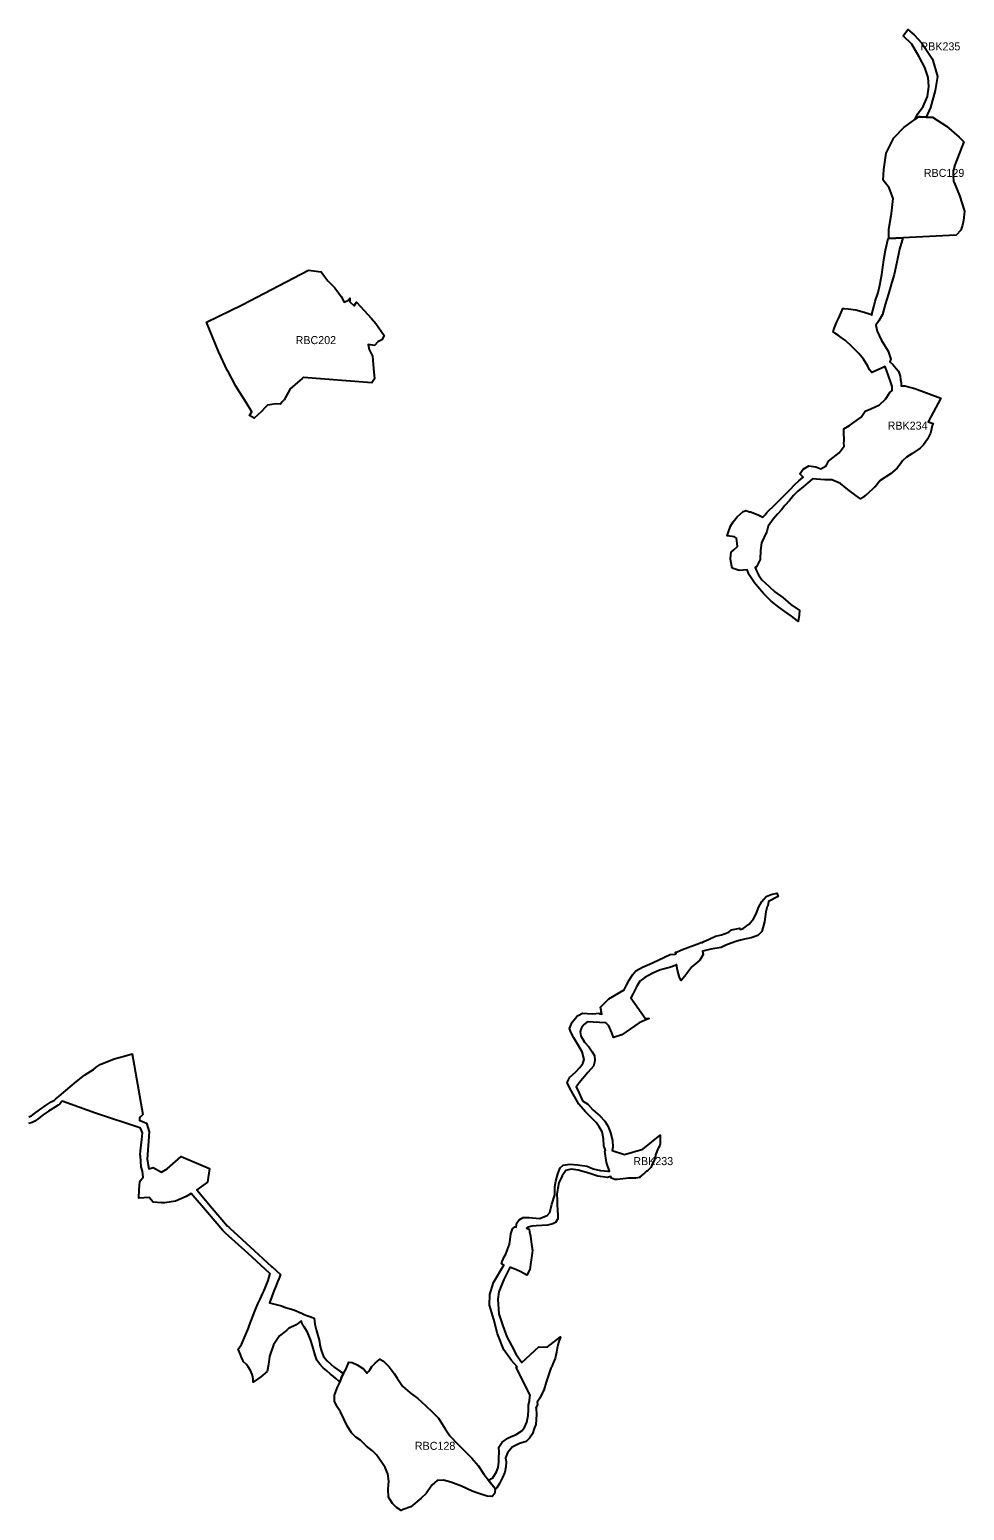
# Model space of a CAD drawing. Extents: x -559776 to -467147, y -1204122 to -1132159.
# Drawn here: x -511258 to -505422, y -1199487 to -1190238 of the extents above; entities that cross this region are included whole.
import ezdxf

# ---------------------------------------------------------------- set-up
doc = ezdxf.new("R2010")
doc.units = 0
doc.layers.add('regionalni_biocentrum_biokoridor', color=7, linetype='Continuous')

msp = doc.modelspace()

# ---------------------------------------------------------------- linework, layer by layer
at = {"layer": 'regionalni_biocentrum_biokoridor'}
for points in [[(-505660.89, -1190784.55), (-505698.22, -1190783.5), (-505708, -1190783.25), (-505730.03, -1190799.2), (-505714.05, -1190765.9), (-505678.12, -1190719.04), (-505651.57, -1190656.56), (-505643.76, -1190594.08), (-505646.88, -1190536.28), (-505668.75, -1190473.8), (-505703.11, -1190408.2), (-505749.97, -1190328.53), (-505802.69, -1190275.82), (-505773.92, -1190238.01), (-505735.92, -1190270.74), (-505687.49, -1190322.28), (-505620.33, -1190422.25), (-505589.09, -1190530.03), (-505603.15, -1190619.07), (-505632.82, -1190725.29)], [(-505660.89, -1190784.55), (-505626.97, -1190785.5), (-505620.62, -1190785.62), (-505532.84, -1190840.37), (-505455.06, -1190909.37), (-505424.16, -1190939.5), (-505482.41, -1191088.37), (-505482.55, -1191092.29), (-505491.41, -1191120.17), (-505491.14, -1191150.61), (-505488.41, -1191185.08), (-505486.11, -1191190.03), (-505486.19, -1191192.25), (-505451, -1191273.62), (-505421.55, -1191372.82), (-505426, -1191429.36), (-505432.27, -1191460.42), (-505444.45, -1191491.07), (-505473.22, -1191522.62), (-505806.41, -1191538.25), (-505893.34, -1191542.25), (-505892.47, -1191483.87), (-505876.34, -1191387.12), (-505866.53, -1191292.5), (-505890.84, -1191226.12), (-505927.72, -1191177.5), (-505925.06, -1191111.5), (-505909.28, -1191009.87), (-505862.37, -1190913.5), (-505800.37, -1190850.12), (-505730.03, -1190799.2), (-505708, -1190783.25), (-505698.22, -1190783.5)], [(-505893.34, -1191542.25), (-505806.41, -1191538.25), (-505809.75, -1191552.12), (-505826.06, -1191608.75), (-505842.84, -1191690), (-505860.09, -1191768.25), (-505875.12, -1191816.37), (-505895.06, -1191887.75), (-505915.09, -1191954.5), (-505933.75, -1192017.25), (-505956.16, -1192056.5), (-505974.47, -1192084.12), (-505965.16, -1192122.5), (-505941.09, -1192174.87), (-505896.81, -1192245.5), (-505881.03, -1192296.62), (-505886.69, -1192312.5), (-505867.22, -1192329.75), (-505848.09, -1192354.87), (-505833.87, -1192372.12), (-505822.94, -1192403.5), (-505819.62, -1192423.12), (-505815.91, -1192443.87), (-505815.37, -1192462.37), (-505793.12, -1192462.37), (-505730.78, -1192479.62), (-505567.81, -1192539.25), (-505647.78, -1192688.87), (-505617.17, -1192699), (-505619.3, -1192706.53), (-505622.74, -1192713.71), (-505626.47, -1192731.92), (-505633.91, -1192758.25), (-505651.13, -1192795.36), (-505677.44, -1192830.73), (-505685.09, -1192840.12), (-505698.34, -1192853.05), (-505749.7, -1192886.84), (-505782.95, -1192907.73), (-505807.63, -1192932.3), (-505820.22, -1192949.59), (-505836.19, -1192971.53), (-505842.1, -1192977.3), (-505883.2, -1193011.91), (-505946.31, -1193054.82), (-505979.57, -1193093.6), (-505981.97, -1193096), (-506031.44, -1193141.25), (-506032.56, -1193142.44), (-506042.87, -1193150.32), (-506047.71, -1193155.68), (-506070.47, -1193167.75), (-506098.94, -1193147.12), (-506150.25, -1193110), (-506194.19, -1193072.87), (-506248.75, -1193049.87), (-506292.37, -1193050.87), (-506371.94, -1193044.37), (-506372.75, -1193045.25), (-506399.44, -1193068.12), (-506428.56, -1193093), (-506460.69, -1193121), (-506487.62, -1193147.25), (-506513.87, -1193178.87), (-506541.72, -1193211.37), (-506563.28, -1193237.75), (-506588.47, -1193264.62), (-506615.75, -1193296.25), (-506647.16, -1193340.5), (-506655.84, -1193372.25), (-506687.44, -1193443.25), (-506693.69, -1193492.12), (-506697.28, -1193547.62), (-506718.66, -1193594.37), (-506726.84, -1193596.87), (-506719.47, -1193618.62), (-506706.31, -1193643.75), (-506685.19, -1193675), (-506639.97, -1193716.37), (-506604.5, -1193750.62), (-506555.75, -1193784.25), (-506504.56, -1193827.75), (-506452.41, -1193863.62), (-506450.47, -1193864.41), (-506453.06, -1193895), (-506459.69, -1193934.71), (-506463.69, -1193931.37), (-506502, -1193901.87), (-506543.41, -1193872.62), (-506580.37, -1193845.75), (-506628.16, -1193808.87), (-506675.12, -1193759.37), (-506711.69, -1193718.62), (-506732.28, -1193694.37), (-506764.97, -1193644.5), (-506777.84, -1193612), (-506828.34, -1193616.25), (-506870.44, -1193601.62), (-506879.84, -1193558.37), (-506881.12, -1193542.62), (-506878.81, -1193519), (-506878.47, -1193502), (-506860.22, -1193487.62), (-506838.44, -1193466.12), (-506839.25, -1193447), (-506843.56, -1193415.37), (-506857.47, -1193405.87), (-506902.94, -1193400.5), (-506895.37, -1193374), (-506882.12, -1193338.75), (-506864.59, -1193311.87), (-506840.75, -1193282.12), (-506802.34, -1193247.62), (-506789.84, -1193243.25), (-506786.47, -1193242), (-506785.97, -1193242.37), (-506762.41, -1193249.25), (-506757.97, -1193250.5), (-506709, -1193269.37), (-506680.56, -1193284), (-506666.12, -1193267.87), (-506655.09, -1193255), (-506640.37, -1193240.25), (-506615.69, -1193217.12), (-506587.62, -1193188.62), (-506560.44, -1193162.37), (-506539.12, -1193140.12), (-506506.69, -1193107.37), (-506482.28, -1193081), (-506454.16, -1193055.5), (-506427.75, -1193032.87), (-506430.97, -1193032.12), (-506448.28, -1193012.12), (-506427.87, -1192984.5), (-506391.75, -1192961.62), (-506349, -1192969.87), (-506318.72, -1192982.25), (-506285.34, -1192962.25), (-506270.78, -1192934.5), (-506240.66, -1192910), (-506204.37, -1192880.75), (-506171.19, -1192840.12), (-506173.41, -1192819.62), (-506172.5, -1192805.5), (-506171.44, -1192789.25), (-506173.53, -1192766.62), (-506174.75, -1192753.75), (-506173.25, -1192730.62), (-506138.59, -1192711.53), (-506065.81, -1192659.12), (-506041.03, -1192621.5), (-506005.62, -1192607.62), (-505951.5, -1192580.62), (-505913.22, -1192545.75), (-505886.41, -1192505.62), (-505872.09, -1192491.37), (-505872.19, -1192489), (-505873.34, -1192468), (-505883.75, -1192436.5), (-505895.78, -1192400.5), (-505917.12, -1192341.37), (-505929.47, -1192347.87), (-505999.37, -1192380.12), (-506013.16, -1192363.62), (-506024.22, -1192339.75), (-506051.09, -1192296), (-506080.78, -1192260.75), (-506125.19, -1192216.87), (-506163.34, -1192179.5), (-506190.25, -1192161.62), (-506208.5, -1192149.5), (-506230.62, -1192133.5), (-506240.31, -1192126.62), (-506234.31, -1192105.5), (-506217.19, -1192062.37), (-506200.5, -1192029.75), (-506179.72, -1191980.12), (-506172.09, -1191980.25), (-506147.47, -1191981.25), (-506098.69, -1191988.12), (-506047.75, -1192002.25), (-506001.59, -1192018.37), (-506000.37, -1192020.87), (-505999.12, -1192016.25), (-505986.78, -1191970), (-505977.62, -1191933.62), (-505960.5, -1191879.12), (-505948.53, -1191834), (-505937.66, -1191767.25), (-505924.56, -1191675.62), (-505914.22, -1191614.87), (-505897.66, -1191542.5)], [(-509361.21, -1191842.67), (-509352.53, -1191851.62), (-509312.78, -1191904.37), (-509294.16, -1191940), (-509270.16, -1191929.37), (-509268.94, -1191930.5), (-509258.59, -1191915.12), (-509258.81, -1191925.75), (-509259.72, -1191938.37), (-509231, -1191963), (-509217.11, -1191940.28), (-509123.33, -1192042.58), (-509095.37, -1192073.09), (-509044.16, -1192147.58), (-509058.12, -1192175.52), (-509083.73, -1192187.16), (-509104.68, -1192210.43), (-509144.26, -1192205.78), (-509137.27, -1192236.04), (-509116.32, -1192277.94), (-509111.66, -1192354.76), (-509104.68, -1192419.94), (-509120.98, -1192443.22), (-509546.98, -1192410.63), (-509547.68, -1192410.57), (-509549.07, -1192410.45), (-509555.76, -1192416.3), (-509630.8, -1192481.93), (-509668.24, -1192549.69), (-509682.51, -1192565.74), (-509691.77, -1192576.74), (-509721.19, -1192574.87), (-509770.94, -1192582.87), (-509773, -1192583.25), (-509787.09, -1192597.5), (-509810.81, -1192622.75), (-509832.47, -1192643.25), (-509856.95, -1192664.59), (-509885.78, -1192647.77), (-509871.52, -1192624.58), (-509906.48, -1192568.01), (-509969.59, -1192465.89), (-510020.08, -1192368.89), (-510020.55, -1192368.85), (-510021.87, -1192368.73), (-510077.73, -1192247.68), (-510154.55, -1192066.11), (-509931.08, -1191956.7), (-509516.72, -1191740.2), (-509438.14, -1191751.17), (-509426.66, -1191766), (-509396.37, -1191806.37)], [(-508351.44, -1199355.87), (-508350.53, -1199350.5), (-508383.03, -1199312.25), (-508392.94, -1199298.62), (-508366.69, -1199284.12), (-508343.69, -1199245.5), (-508332.91, -1199218.62), (-508329, -1199184.25), (-508327.91, -1199158.62), (-508326.47, -1199125.37), (-508327.69, -1199092.75), (-508307.16, -1199060.37), (-508272.78, -1199035.5), (-508254.84, -1199028.62), (-508220.5, -1199012.62), (-508185.44, -1198990), (-508168.44, -1198969.87), (-508152.69, -1198935.37), (-508145.09, -1198894.75), (-508143.34, -1198859.25), (-508142.84, -1198827.12), (-508137.31, -1198804.62), (-508134.12, -1198775.25), (-508132.55, -1198766.62), (-508219.59, -1198595.21), (-508213.43, -1198589.54), (-508250.18, -1198551.73), (-508296.88, -1198484.11), (-508337.13, -1198384.28), (-508359.67, -1198295.72), (-508387.04, -1198205.55), (-508385.43, -1198137.93), (-508361.28, -1198063.86), (-508297.63, -1197954.75), (-508311.75, -1197947.87), (-508307.25, -1197932.75), (-508295, -1197902.75), (-508285.62, -1197885.62), (-508273.34, -1197857.25), (-508262.19, -1197824.12), (-508257.75, -1197794.75), (-508253.53, -1197760.12), (-508242.69, -1197727.5), (-508227.87, -1197716.75), (-508221.09, -1197718.5), (-508216.66, -1197690.75), (-508201.34, -1197671.62), (-508176.75, -1197657.75), (-508138.62, -1197658.5), (-508074.84, -1197663), (-508025.69, -1197645.87), (-508009.44, -1197625.62), (-507996.5, -1197574.62), (-507977.91, -1197516.75), (-507977.97, -1197465.12), (-507972.62, -1197431.37), (-507960.91, -1197385.5), (-507945.91, -1197347), (-507926.62, -1197330.5), (-507884.06, -1197325.5), (-507837.47, -1197328.12), (-507776, -1197338), (-507738.72, -1197353.75), (-507693.06, -1197364.62), (-507648.75, -1197368.75), (-507636.34, -1197368.66), (-507655.59, -1197313.64), (-507667.49, -1197243.15), (-507662.98, -1197238.33), (-507673.34, -1197209.12), (-507675.5, -1197166.87), (-507682.94, -1197122), (-507702.59, -1197090.87), (-507720.69, -1197064.87), (-507765.75, -1197019.25), (-507786.87, -1196998.37), (-507828.37, -1196949.5), (-507856.94, -1196901.62), (-507882.72, -1196854), (-507900.78, -1196813.5), (-507885.5, -1196780.37), (-507849.78, -1196749.62), (-507821.78, -1196720.87), (-507803.19, -1196694.87), (-507794.84, -1196670.75), (-507807.84, -1196623.5), (-507840.5, -1196566.5), (-507860.16, -1196535.5), (-507877.62, -1196504.87), (-507887.25, -1196477.25), (-507871, -1196437.37), (-507858.78, -1196422.37), (-507842.03, -1196401.62), (-507833.91, -1196396.87), (-507806.12, -1196380.37), (-507746.47, -1196385.25), (-507697.84, -1196382.37), (-507700.21, -1196386.25), (-507685.65, -1196387.61), (-507693.9, -1196343.24), (-507641.73, -1196292.14), (-507545.34, -1196235.33), (-507541.5, -1196226.87), (-507531.53, -1196206.75), (-507515, -1196176), (-507494, -1196142.5), (-507472.72, -1196117.12), (-507430.44, -1196093.62), (-507387, -1196075.75), (-507337.31, -1196052), (-507289.72, -1196028.87), (-507259.06, -1196015.62), (-507230.03, -1196012.12), (-507224.53, -1196010), (-507220.37, -1196008.37), (-507222.12, -1196006.5), (-507226.09, -1196002.37), (-507226.63, -1196001.66), (-507215.67, -1195997.51), (-507181.87, -1195984.7), (-507075.43, -1195944.38), (-507066.07, -1195940.84), (-507058.72, -1195939.12), (-507047.69, -1195933.88), (-507019.56, -1195920.5), (-506975, -1195901.25), (-506938.25, -1195892.37), (-506891.5, -1195874.5), (-506875.41, -1195861.75), (-506875.38, -1195861.03), (-506823.49, -1195850.02), (-506820.66, -1195858.12), (-506803.72, -1195852.37), (-506765.53, -1195825.37), (-506738.41, -1195791.75), (-506720.12, -1195757.25), (-506707.37, -1195722), (-506686.03, -1195683.62), (-506659.87, -1195653.25), (-506628.16, -1195639.75), (-506592.43, -1195631.29), (-506584.69, -1195652.75), (-506644.69, -1195683.5), (-506649.4, -1195711.47), (-506652.47, -1195716.12), (-506660.69, -1195748.37), (-506669.34, -1195810.87), (-506685.44, -1195870.37), (-506711.87, -1195897.12), (-506752.72, -1195910.12), (-506794.06, -1195919.37), (-506819.97, -1195925.87), (-506843, -1195931.5), (-506849.09, -1195933.75), (-506876.91, -1195943.87), (-506910.78, -1195955.62), (-506939.78, -1195970.62), (-507005, -1195982.5), (-507054.37, -1195993.75), (-507057.41, -1195994.62), (-507052.44, -1196014.75), (-507073.09, -1196050.62), (-507122.34, -1196091), (-507167.97, -1196150.37), (-507189.84, -1196177.62), (-507200.62, -1196158.87), (-507213.37, -1196112.37), (-507218.91, -1196078.37), (-507223.81, -1196080.62), (-507248.44, -1196091.25), (-507324.97, -1196112.87), (-507370.12, -1196133.62), (-507416.62, -1196159.37), (-507448.37, -1196181.25), (-507469.22, -1196216), (-507491.84, -1196262.37), (-507503.23, -1196285.36), (-507414.13, -1196412.87), (-507390.55, -1196415.06), (-507415.11, -1196424.61), (-507451.94, -1196440.98), (-507561.07, -1196517.37), (-507612.9, -1196533.74), (-507623.82, -1196503.73), (-507641.55, -1196460.08), (-507657.71, -1196443.57), (-507662.39, -1196440.97), (-507662.34, -1196442.1), (-507776.28, -1196435.37), (-507794.34, -1196450.37), (-507795.53, -1196451.87), (-507810.69, -1196469.62), (-507813.62, -1196478.12), (-507820.44, -1196498.12), (-507816.44, -1196522.12), (-507792.66, -1196562.25), (-507765.81, -1196591.5), (-507746.53, -1196623.62), (-507730.16, -1196645.5), (-507728.81, -1196679.12), (-507737.62, -1196711.87), (-507771.66, -1196752.37), (-507803.59, -1196789), (-507827.75, -1196816), (-507845.94, -1196842.87), (-507833.91, -1196866.25), (-507805.12, -1196928.75), (-507771.78, -1196950.25), (-507740.44, -1196986), (-507697.56, -1197023.37), (-507666.12, -1197056.62), (-507645.72, -1197089.62), (-507630.25, -1197128.5), (-507618.16, -1197176.75), (-507617.34, -1197217.62), (-507621.23, -1197239.2), (-507542.98, -1197264.2), (-507428.55, -1197231.25), (-507321.43, -1197142.44), (-507321.43, -1197197.52), (-507322.93, -1197207.05), (-507325.31, -1197211.97), (-507331.83, -1197222.44), (-507332.9, -1197224.7), (-507342.47, -1197244.9), (-507349.6, -1197267.01), (-507350.6, -1197271.65), (-507355.69, -1197295.26), (-507359.95, -1197305.46), (-507370.83, -1197324.02), (-507375.85, -1197336.05), (-507377.01, -1197338.84), (-507379.62, -1197345.09), (-507379.85, -1197345.85), (-507383.12, -1197349.87), (-507397.28, -1197363.25), (-507403.88, -1197368.02), (-507405.56, -1197368.91), (-507407.88, -1197370.91), (-507412.84, -1197374.5), (-507419.81, -1197380.5), (-507424.63, -1197385.39), (-507428.95, -1197389.12), (-507447.71, -1197403.58), (-507447.79, -1197408.64), (-507447.96, -1197408.81), (-507473.41, -1197412.52), (-507519.18, -1197411.6), (-507586.93, -1197420.76), (-507604.32, -1197419.84), (-507625.38, -1197411.6), (-507630.28, -1197402.12), (-507650.09, -1197408.75), (-507710.84, -1197399.25), (-507767.19, -1197380.37), (-507833.37, -1197362.25), (-507876, -1197355.25), (-507910.12, -1197364.25), (-507932.84, -1197397.37), (-507952.94, -1197440.75), (-507960.19, -1197473.5), (-507965.75, -1197512.25), (-507963.97, -1197550), (-507963.19, -1197580.5), (-507962.25, -1197608), (-507960.53, -1197647.87), (-507960.91, -1197666.62), (-507973.62, -1197689.12), (-507990.37, -1197696.75), (-508023.62, -1197704.87), (-508060.5, -1197707.87), (-508095.25, -1197710.5), (-508123.12, -1197711.5), (-508148.06, -1197717.12), (-508154.69, -1197724), (-508139.91, -1197730), (-508135.97, -1197747.5), (-508131.06, -1197774.12), (-508123.47, -1197826.87), (-508119.12, -1197862.62), (-508122.69, -1197894.87), (-508127.94, -1197936.75), (-508134.94, -1197982), (-508153.03, -1198017), (-508191.06, -1197997.62), (-508222.03, -1197982.62), (-508256.47, -1197970.37), (-508259.32, -1197969.43), (-508296.88, -1198044.54), (-508329.08, -1198121.83), (-508335.52, -1198168.52), (-508327.47, -1198258.69), (-508303.32, -1198334.37), (-508279.17, -1198403.6), (-508250.18, -1198456.74), (-508219.59, -1198513.09), (-508184.96, -1198563.36), (-508079.51, -1198466.4), (-508026.37, -1198468.01), (-507942.82, -1198403.02), (-507955.41, -1198438.95), (-507964.45, -1198474.56), (-507967.39, -1198498.9), (-507977.4, -1198539.3), (-507991.46, -1198570.89), (-507998.41, -1198588.33), (-507999.27, -1198590.7), (-508003.83, -1198598.43), (-508032.81, -1198685.38), (-508047.22, -1198735.22), (-508069.02, -1198775.91), (-508072.9, -1198786.98), (-508088.71, -1198811.05), (-508086.46, -1198824.74), (-508087.31, -1198826.94), (-508097.69, -1198845.87), (-508095.26, -1198851.55), (-508092.48, -1198887.34), (-508098.28, -1198949.9), (-508107.84, -1198975.25), (-508117.37, -1199009.5), (-508136.03, -1199035.75), (-508158.19, -1199056.12), (-508198.31, -1199069.12), (-508244.59, -1199091.25), (-508273.69, -1199127.87), (-508286.37, -1199159), (-508283.25, -1199185.5), (-508284.72, -1199215.37), (-508290.06, -1199247.37), (-508305.47, -1199281.5), (-508325.16, -1199318.5), (-508341.53, -1199345.12)], [(-509012.84, -1198590.37), (-508982.69, -1198632.62), (-508963.97, -1198661.25), (-508929.09, -1198711.62), (-508881.22, -1198752), (-508834.72, -1198789.12), (-508813.12, -1198806.87), (-508781.44, -1198836.37), (-508746.5, -1198868.62), (-508704.47, -1198912), (-508663.87, -1198977.87), (-508634.72, -1199021.5), (-508583.81, -1199072.87), (-508540.41, -1199117.37), (-508496.78, -1199160.5), (-508457.5, -1199206.87), (-508421, -1199260.25), (-508392.94, -1199298.62), (-508383.03, -1199312.25), (-508350.53, -1199350.5), (-508351.44, -1199355.87), (-508356.25, -1199383.37), (-508369.56, -1199401), (-508401.91, -1199397.5), (-508447.03, -1199382.75), (-508494.41, -1199367.75), (-508562.31, -1199334.75), (-508627.66, -1199310.87), (-508674.19, -1199298.75), (-508713.22, -1199300.62), (-508747.5, -1199330.37), (-508781.91, -1199380.75), (-508813.78, -1199409.75), (-508877.75, -1199463.87), (-508925.78, -1199482.12), (-508938.81, -1199487), (-508967.03, -1199469), (-508984.12, -1199452.25), (-508993.34, -1199443.12), (-509017.41, -1199405.12), (-509018.69, -1199354.87), (-509016.16, -1199304.87), (-509021.22, -1199258), (-509039.12, -1199220), (-509062.34, -1199181.25), (-509092.78, -1199139.5), (-509118.06, -1199115.25), (-509155.31, -1199085), (-509191.75, -1199049), (-509221.41, -1199030.37), (-509247.31, -1199003.5), (-509276.19, -1198957.87), (-509296.47, -1198914.87), (-509317.56, -1198872.12), (-509338.59, -1198839.87), (-509354.09, -1198804.75), (-509354.78, -1198768.37), (-509335.87, -1198716.87), (-509324.25, -1198692.37), (-509320.06, -1198683.62), (-509309, -1198651.25), (-509302.34, -1198639.37), (-509298.32, -1198632.27), (-509281.5, -1198602.62), (-509265.34, -1198561.5), (-509244.94, -1198564.12), (-509212, -1198577.87), (-509174.12, -1198603.62), (-509150.56, -1198629.12), (-509148.72, -1198625.25), (-509142.19, -1198619), (-509134.09, -1198609.25), (-509122, -1198589.12), (-509100.59, -1198566.87), (-509070.97, -1198542.87), (-509048.09, -1198555.37)]]:
    msp.add_lwpolyline(points, close=True, dxfattribs=at)
msp.add_lwpolyline([(-511263.4, -1197029.64), (-511246.79, -1197022.26), (-511227, -1197007.16), (-511196.39, -1196984.88), (-511162.05, -1196959.77), (-511129.84, -1196939.96), (-511123.37, -1196935.78), (-511103.78, -1196923.89), (-511094.53, -1196916.23), (-511073.58, -1196898.88), (-511005.04, -1196841.28), (-510965.84, -1196808.78), (-510915.22, -1196769.2), (-510858.43, -1196733.83), (-510841.82, -1196718.55), (-510816.83, -1196701.43), (-510781.71, -1196686.73), (-510754.86, -1196676.16), (-510729.36, -1196667.6), (-510668.24, -1196649.87), (-510618.75, -1196635.43), (-510551.07, -1197013.62), (-510564.32, -1197027.05), (-510572.85, -1197037.86), (-510571, -1197051.96), (-510568.09, -1197052.66), (-510528.28, -1197068.85), (-510511.76, -1197122.38), (-510524.76, -1197292.36), (-510514.49, -1197353.23), (-510499.94, -1197348.62), (-510486.74, -1197344.44), (-510433.91, -1197374.42), (-510400.29, -1197354.04), (-510311.43, -1197277.3), (-510134.91, -1197351.64), (-510148.12, -1197436.77), (-510213.66, -1197485.65), (-510117.83, -1197598.82), (-510021.99, -1197711.99), (-510016.77, -1197716.76), (-510008.79, -1197724.04), (-509855.01, -1197864.46), (-509747.03, -1197963.05), (-509743.7, -1197966.1), (-509691.97, -1198013.32), (-509702, -1198040.07), (-509710.14, -1198060.4), (-509718.07, -1198082.64), (-509730.33, -1198112.33), (-509760.56, -1198189.75), (-509686.22, -1198209.33), (-509660.37, -1198219.13), (-509607.77, -1198235.18), (-509560.36, -1198255.68), (-509554.9, -1198258.38), (-509526.73, -1198269.7), (-509521.84, -1198271.67), (-509508.99, -1198276.84), (-509491.44, -1198282.24), (-509481.08, -1198286.29), (-509477.93, -1198324.1), (-509466.68, -1198366.41), (-509454.98, -1198409.62), (-509449.12, -1198431.67), (-509445.44, -1198455.25), (-509435.47, -1198493.13), (-509423.44, -1198525.63), (-509401.05, -1198552.2), (-509355.77, -1198592.86), (-509314.35, -1198621.91), (-509297.61, -1198631.02), (-509298.32, -1198632.27), (-509309, -1198651.25), (-509318.21, -1198678.19), (-509326.86, -1198679.88), (-509346.48, -1198664.11), (-509362.73, -1198649.01), (-509379.38, -1198636.23), (-509402.6, -1198615.32), (-509425.68, -1198596.83), (-509446.84, -1198573.88), (-509463.97, -1198548.88), (-509475.94, -1198517.63), (-509491.81, -1198459.13), (-509502.41, -1198426.72), (-509509.59, -1198405.66), (-509522.74, -1198374), (-509536.74, -1198351.72), (-509544.5, -1198340.62), (-509547.58, -1198336.26), (-509556.72, -1198323.75), (-509561.2, -1198305.64), (-509567.16, -1198306.56), (-509593.51, -1198327), (-509642.54, -1198350.18), (-509655.02, -1198362.66), (-509696.92, -1198397.43), (-509734.36, -1198452.7), (-509759.32, -1198524.91), (-509767.35, -1198576.61), (-509774.72, -1198619), (-509815.34, -1198652.63), (-509863.28, -1198687.08), (-509862.67, -1198667.53), (-509865.91, -1198645.53), (-509868.65, -1198639.23), (-509879.79, -1198613.4), (-509892.93, -1198591.32), (-509903.63, -1198576.17), (-509923.85, -1198556.41), (-509925.64, -1198552.04), (-509928.11, -1198546.11), (-509930.27, -1198541.24), (-509936.48, -1198525.29), (-509941.71, -1198512.32), (-509955.47, -1198480.3), (-509955.59, -1198480.01), (-509936.01, -1198450.03), (-509892.14, -1198349.84), (-509886.26, -1198334.39), (-509876.15, -1198307.99), (-509872.25, -1198296.88), (-509851.89, -1198243.5), (-509832.15, -1198197.16), (-509830.13, -1198193.26), (-509818.79, -1198168.3), (-509801.09, -1198129.35), (-509793.49, -1198112.88), (-509768.79, -1198050.41), (-509757.82, -1198013.62), (-509756.37, -1198008.7), (-509759.6, -1198005.74), (-509893.68, -1197883.32), (-510034.51, -1197754.72), (-510043.71, -1197746.32), (-510050.86, -1197739.79), (-510147.53, -1197625.65), (-510250.19, -1197507.51), (-510281.41, -1197525.5), (-510346.25, -1197555.47), (-510413.5, -1197566.26), (-510428.69, -1197565.52), (-510434.45, -1197564.73), (-510434.98, -1197565.21), (-510486.74, -1197562.67), (-510510.76, -1197532.69), (-510575.77, -1197536.05), (-510575.35, -1197526.99), (-510571.96, -1197454.24), (-510569.41, -1197437.48), (-510568.14, -1197431.25), (-510565.2, -1197427.21), (-510549.15, -1197405.21), (-510552.75, -1197368.23), (-510562.08, -1197340.65), (-510563.77, -1197308.73), (-510566.15, -1197272.15), (-510568.51, -1197266.36), (-510565.89, -1197240.84), (-510557.39, -1197169.79), (-510552.72, -1197128.59), (-510565.63, -1197099.2), (-510569.99, -1197098.46), (-510845.99, -1197006.03), (-511055.57, -1196930.31), (-511069.02, -1196947.04), (-511080.52, -1196956.56), (-511102.45, -1196969.87), (-511139.67, -1196992.96), (-511172.81, -1197017.19), (-511203.09, -1197039.23), (-511226.26, -1197056.91), (-511241.64, -1197063.74), (-511247.57, -1197066.38), (-511264.77, -1197070.22)], dxfattribs=at)

# ---------------------------------------------------------------- texts
for s, p in [('RBK235', (-505695.89, -1190367.66)), ('RBC129', (-505674.63, -1191158.12)), ('RBC202', (-509597.17, -1192202.39)), ('RBK234', (-505900.69, -1192736.48)), ('RBK233', (-507488.82, -1197330.41)), ('RBC128', (-508852.66, -1199108.72))]:
    msp.add_text(s, height=50, dxfattribs=at).set_placement(p)

doc.saveas('drawing.dxf')
